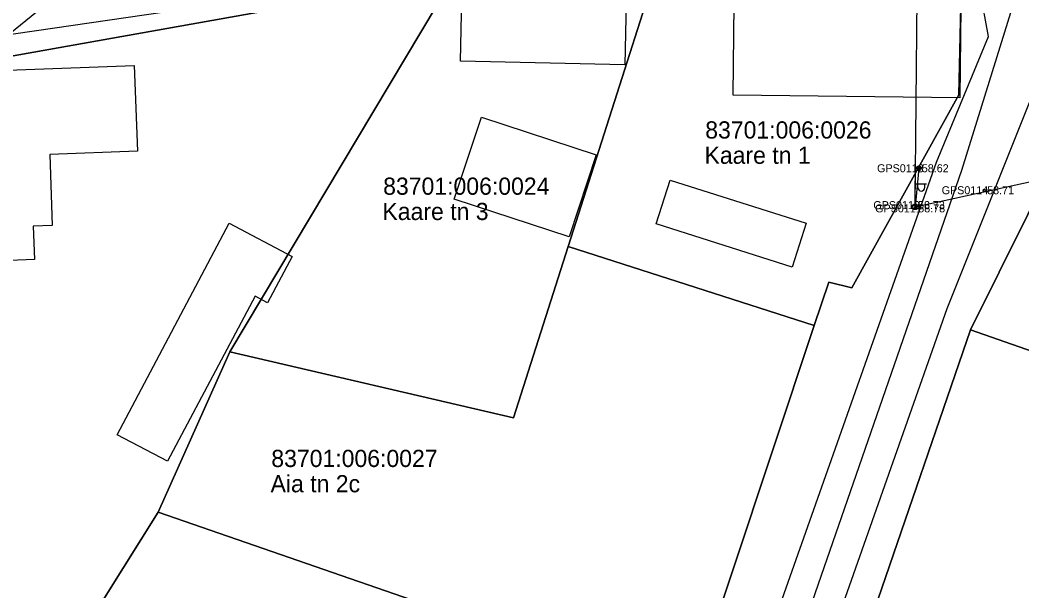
# Model space of a CAD drawing. Extents: x 580119 to 583377, y 6518915 to 6520820.
# Drawn here: x 581780.8 to 581868.2, y 6519692.3 to 6519742.1 of the extents above; entities that cross this region are included whole.
import ezdxf

# ---------------------------------------------------------------- set-up
doc = ezdxf.new("R2010")
doc.units = 0
for name, color, linetype in [('Hoone Elu- või ühiskondlik hoone', 7, 'Continuous'), ('Hoone Kõrval- või tootmishoone', 7, 'Continuous'), ('L_AADRESS', 7, 'Continuous'), ('MAAMUDEL', 7, 'Continuous'), ('MOOTKORG-EH2000', 7, 'Continuous'), ('MOOTMPUNKT', 7, 'Continuous'), ('MOOTNR', 7, 'Continuous'), ('MPOHULIIN', 7, 'Continuous'), ('PIIR', 7, 'Continuous'), ('POST', 7, 'Continuous'), ('Tee Liiklusala', 7, 'Continuous'), ('Tee Tänav Püsikate', 7, 'Continuous'), ('TUNNUS', 7, 'Continuous')]:
    doc.layers.add(name, color=color, linetype=linetype)

msp = doc.modelspace()

# ---------------------------------------------------------------- linework, layer by layer
at = {"layer": 'Hoone Elu- või ühiskondlik hoone'}
for points in [[(581833.758, 6519746.511), (581833.573, 6519738.195), (581819.242, 6519738.513), (581819.434, 6519746.834)], [(581862.914, 6519745.884), (581862.786, 6519735.305), (581843.022, 6519735.524), (581843.135, 6519746.116)], [(581790.793, 6519738.118), (581791.069, 6519730.649), (581783.423, 6519730.364), (581783.652, 6519724.177), (581781.985, 6519724.114), (581782.092, 6519721.196), (581772.594, 6519720.836), (581772.197, 6519731.813), (581770.502, 6519731.75), (581770.294, 6519737.362)]]:
    msp.add_lwpolyline(points, close=True, dxfattribs=at)
at = {"layer": 'Hoone Kõrval- või tootmishoone'}
for points in [[(581831.077, 6519730.322), (581828.716, 6519723.166), (581818.712, 6519726.454), (581821.078, 6519733.612)], [(581849.403, 6519724.358), (581848.188, 6519720.53), (581836.309, 6519724.3), (581837.523, 6519728.127)], [(581804.56, 6519721.476), (581802.42, 6519717.437), (581801.33, 6519718.015), (581793.697, 6519703.598), (581789.302, 6519705.921), (581799.081, 6519724.374)]]:
    msp.add_lwpolyline(points, close=True, dxfattribs=at)
at = {"layer": 'MOOTMPUNKT'}
for centre in [(581859.221, 6519729.161), (581864.922, 6519727.244), (581858.892, 6519725.944), (581858.912, 6519725.663)]:
    msp.add_circle(centre, 0.1, dxfattribs=at)
at = {"layer": 'MPOHULIIN'}
for p, q in [((581858.902, 6519725.803), (581859.098, 6519746.426)), ((581777.925, 6519739.278), (581786.126, 6519745.969)), ((581858.902, 6519725.803), (581899.654, 6519734.693))]:
    msp.add_line(p, q, dxfattribs=at)
at = {"layer": 'PIIR'}
msp.add_lwpolyline([(581707.45, 6519738.72), (581736.84, 6519743.64), (581785.72, 6519751.16), (581797.39, 6519753.15), (581818.63, 6519745.83), (581759.12, 6519735.22), (581739.49, 6519732.55), (581707.53, 6519728.73)], dxfattribs=at)
for points in [[(581818.63, 6519745.83), (581818.91, 6519746.03), (581821.06, 6519746.26), (581836.27, 6519746.21), (581828.64, 6519722.33), (581823.87, 6519707.4), (581799.14, 6519713.16)], [(581836.27, 6519746.21), (581862.95, 6519745.89), (581862.7, 6519735.58), (581853.38, 6519718.73), (581851.38, 6519719.23), (581850.1, 6519715.45), (581828.64, 6519722.33)], [(581757.43, 6519646.61), (581749.03, 6519634.03), (581724.56, 6519646.71), (581738.8, 6519670.79), (581758.6, 6519703.51), (581759.12, 6519735.22), (581818.63, 6519745.83), (581799.14, 6519713.16), (581792.88, 6519699.16), (581778.97, 6519676.98), (581764.34, 6519656.94)], [(581862.7, 6519735.58), (581862.95, 6519745.89), (581876.19, 6519740.16), (581863.74, 6519715.07), (581855.33, 6519690.59), (581838.33, 6519642.8), (581821.94, 6519597.83), (581818.32, 6519573.11), (581803.96, 6519517.1), (581795.63, 6519521.82), (581799.07, 6519533.63), (581809.3, 6519578.74), (581818.49, 6519614.04), (581825.04, 6519632.45), (581822.37, 6519633.64), (581830.85, 6519658.81), (581839.33, 6519683.07), (581850.1, 6519715.45), (581851.38, 6519719.23), (581853.38, 6519718.73)], [(581876.19, 6519740.16), (581940.85, 6519717.73), (581928.38, 6519692.46), (581863.74, 6519715.07)], [(581828.64, 6519722.33), (581850.1, 6519715.45), (581839.33, 6519683.07), (581792.88, 6519699.16), (581799.14, 6519713.16), (581823.87, 6519707.4)], [(581863.74, 6519715.07), (581928.38, 6519692.46), (581916.9, 6519667.86), (581855.33, 6519690.59)], [(581792.88, 6519699.16), (581839.33, 6519683.07), (581830.85, 6519658.81), (581778.97, 6519676.98)]]:
    msp.add_lwpolyline(points, close=True, dxfattribs=at)
at = {"layer": 'POST'}
for p, q in [((581858.902, 6519726.053), (581858.902, 6519728.053)), ((581858.902, 6519727.803), (581859.902, 6519727.803)), ((581859.129, 6519727.482), (581859.129, 6519727.803)), ((581859.742, 6519727.482), (581859.742, 6519727.803)), ((581858.902, 6519725.803), (581858.902, 6519725.803))]:
    msp.add_line(p, q, dxfattribs=at)
msp.add_lwpolyline([(581859.221, 6519729.161), (581858.902, 6519725.803)], dxfattribs=at)
for centre, radius in [((581859.221, 6519729.161), 0.2), ((581858.902, 6519725.803), 0.25)]:
    msp.add_circle(centre, radius, dxfattribs=at)
msp.add_arc((581859.435, 6519727.482), 0.306, 180, 0, dxfattribs=at)
at = {"layer": 'Tee Liiklusala'}
for points in [[(581813.136, 6519581.734), (581814.609, 6519596.327), (581820.112, 6519615.445), (581823.934, 6519625.234), (581847.476, 6519692.072), (581860.775, 6519729.697), (581865.294, 6519740.669), (581864.575, 6519744.639), (581863.32, 6519746.334), (581841.102, 6519747.218), (581827.648, 6519749.647), (581814.586, 6519754.011), (581808.571, 6519747.528), (581803.693, 6519744.783), (581798.267, 6519743.483), (581714.065, 6519731.241), (581710.969, 6519730.467)], [(581870.304, 6519738.502), (581861.668, 6519716.888), (581850.077, 6519683.967), (581831.427, 6519629.059), (581825.007, 6519611.776), (581820.727, 6519595.564), (581820.422, 6519590.516), (581822.21, 6519586.77)]]:
    msp.add_lwpolyline(points, dxfattribs=at)
at = {"layer": 'Tee Tänav Püsikate'}
msp.add_lwpolyline([(581868.696, 6519747.532), (581862.937, 6519728.965), (581847.63, 6519684.731), (581827.451, 6519626.917), (581822.865, 6519614.069), (581816.904, 6519592.657), (581815.572, 6519581.172)], dxfattribs=at)

# ---------------------------------------------------------------- texts
at = {"layer": 'L_AADRESS'}
for s, p in [('Kaare tn 1', (581840.532, 6519729.55)), ('Kaare tn 3', (581812.442, 6519724.645)), ('Aia tn 2c', (581802.687, 6519700.895))]:
    msp.add_text(s, height=1.5, dxfattribs=at).set_placement(p)
at = {"layer": 'MAAMUDEL'}
msp.add_text(' tv', height=0.35, dxfattribs=at).set_placement((581864.922, 6519727.069))
at = {"layer": 'MOOTKORG-EH2000'}
for s, p in [(' 58.62', (581859.221, 6519728.811)), (' 58.71', (581864.922, 6519726.894)), (' 58.73', (581858.892, 6519725.594)), (' 58.78', (581858.912, 6519725.313))]:
    msp.add_text(s, height=0.7, dxfattribs=at).set_placement(p)
at = {"layer": 'MOOTNR'}
for s, p in [('GPS0113 ', (581855.582, 6519728.811)), ('GPS0114 ', (581861.212, 6519726.894)), ('GPS0112 ', (581855.252, 6519725.594)), ('GPS0111 ', (581855.413, 6519725.313))]:
    msp.add_text(s, height=0.7, dxfattribs=at).set_placement(p)
at = {"layer": 'TUNNUS'}
for s, p in [('83701:006:0026', (581840.595, 6519731.755)), ('83701:006:0024', (581812.505, 6519726.85)), ('83701:006:0027', (581802.75, 6519703.1))]:
    msp.add_text(s, height=1.5, dxfattribs=at).set_placement(p)

doc.saveas('drawing.dxf')
